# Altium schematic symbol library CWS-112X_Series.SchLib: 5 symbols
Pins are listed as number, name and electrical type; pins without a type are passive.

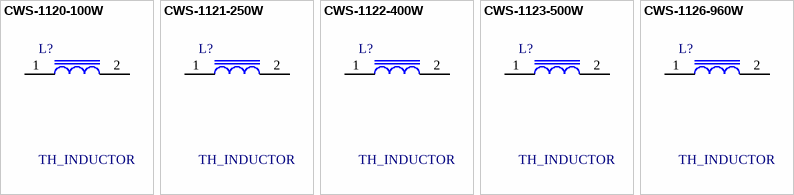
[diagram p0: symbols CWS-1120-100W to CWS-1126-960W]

## CWS-1120-100W
designator L?, comment TH_INDUCTOR
POWER INDUCTOR 7 A, 3.3 uH, 3.6 mOhms, OD 21.59 mm, HT 10.16 mm; Manufacturer #1: CWS; Description: POWER INDUCTOR 1.5 A, 4 mH, 0.85 ohms, OD 33 mm, HT 14 mm; OD: 33 mm; Current: 1.5 A; DCR: 0.85 ohms; Inductance: 4 mH
footprint CWS-1120-100W
pins: 1, 2

## CWS-1121-250W
designator L?, comment TH_INDUCTOR
POWER INDUCTOR 7 A, 3.3 uH, 3.6 mOhms, OD 21.59 mm, HT 10.16 mm; Manufacturer #1: CWS; Description: POWER INDUCTOR 2 A, 4.5 mH, 0.8 ohms, OD 33 mm, HT 18.5 mm; OD: 33 mm; Current: 2 A; DCR: 0.8 ohms; Inductance: 4.5 mH
footprint CWS-1121-250W
pins: 1, 2

## CWS-1122-400W
designator L?, comment TH_INDUCTOR
POWER INDUCTOR 7 A, 3.3 uH, 3.6 mOhms, OD 21.59 mm, HT 10.16 mm; Manufacturer #1: CWS; Description: POWER INDUCTOR 3 A, 2.9 mH, 0.5 ohms, OD 31 mm, HT 13.5 mm; OD: 31 mm; Current: 3 A; DCR: 0.5 ohms; Inductance: 2.9 mH
footprint CWS-1122-400W
pins: 1, 2

## CWS-1123-500W
designator L?, comment TH_INDUCTOR
POWER INDUCTOR 7 A, 3.3 uH, 3.6 mOhms, OD 21.59 mm, HT 10.16 mm; Manufacturer #1: CWS; Description: POWER INDUCTOR 4 A, 2.4 mH, 0.45 ohms, OD 33 mm, HT 17 mm; OD: 33 mm; Current: 4 A; DCR: 0.45 ohms; Inductance: 2.4 mH
footprint CWS-1123-500W
pins: 1, 2

## CWS-1126-960W
designator L?, comment TH_INDUCTOR
POWER INDUCTOR 7 A, 3.3 uH, 3.6 mOhms, OD 21.59 mm, HT 10.16 mm; Manufacturer #1: CWS; Description: POWER INDUCTOR 8 A, 2 mH, 0.2 ohms, OD 40 mm, HT 21 mm; OD: 40 mm; Current: 8 A; DCR: 0.2 ohms; Inductance: 2 mH
footprint CWS-1126-960W
pins: 1, 2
